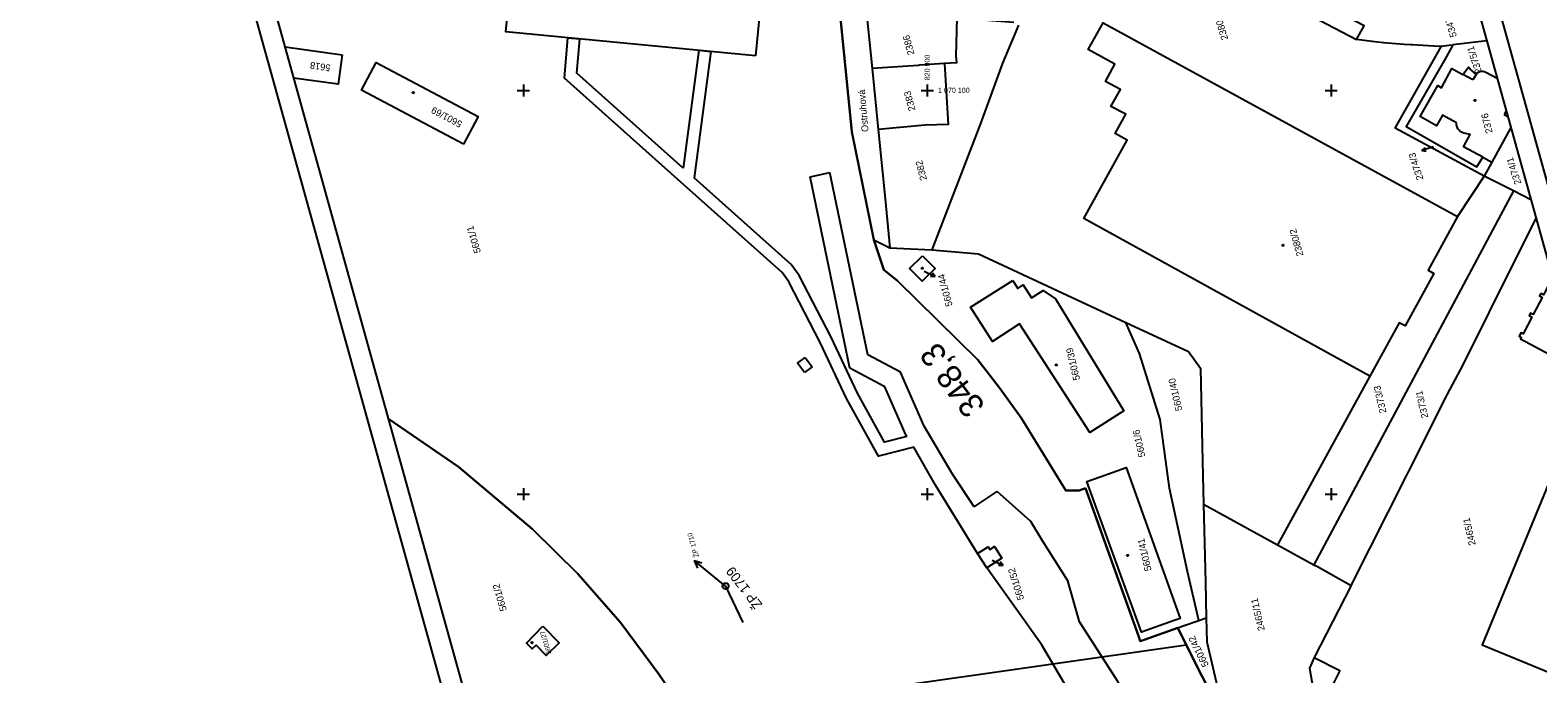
# Model space of a CAD drawing. Extents: x -821122 to -820555, y -1070892 to -1069801.
# Drawn here: x -821122.1 to -820748.9, y -1070244.5 to -1070085.1 of the extents above; entities that cross this region are included whole.
import ezdxf

# ---------------------------------------------------------------- set-up
doc = ezdxf.new("R2010")
doc.units = 0
for name, color, linetype in [('Hranice drážního pozemku', 7, 'Continuous'), ('Hranice parcel', 7, 'Continuous'), ('Katastrální hranice', 7, 'Continuous'), ('Parcelní čísla', 7, 'Continuous'), ('Pop  PČ popisy', 7, 'Continuous'), ('Ram', 7, 'Continuous'), ('Sttaniceni a namezniky', 7, 'Continuous'), ('Vnitřní kresba', 7, 'Continuous'), ('Vrstva 61', 7, 'Continuous'), ('Vrstva 63', 7, 'Continuous'), ('ZBP', 7, 'Continuous'), ('Značky budov', 7, 'Continuous')]:
    doc.layers.add(name, color=color, linetype=linetype)

msp = doc.modelspace()

# ---------------------------------------------------------------- linework, layer by layer
at = {"layer": 'Hranice drážního pozemku'}
for p, q in [((-820907.37, -1070147.11), (-820887.52, -1070166.75)), ((-820860.8, -1070198.48), (-820847.74, -1070235.07)), ((-820838.01, -1070233.1), (-820835.88, -1070237.32)), ((-820835.88, -1070237.32), (-820826.1, -1070256.7))]:
    msp.add_line(p, q, dxfattribs=at)
for points in [[(-820922.5, -1070043.2), (-820922.83, -1070068.79), (-820918.68, -1070110.25), (-820913.23, -1070137.01)], [(-820913.23, -1070137.01), (-820910.8, -1070144.4), (-820907.37, -1070147.11)], [(-820887.52, -1070166.75), (-820882.1, -1070173.67), (-820876.76, -1070181.11), (-820865.67, -1070199.11), (-820862.44, -1070199.07), (-820860.8, -1070198.48)], [(-820959.73, -1070254.91), (-820961.88, -1070251.33), (-820966.49, -1070244.53), (-820975.99, -1070231.76), (-820986.52, -1070219.72), (-820997.71, -1070208.62), (-821016.02, -1070193.21), (-821033.38, -1070181.32)], [(-820847.74, -1070235.07), (-820847.27, -1070236.4), (-820846.3, -1070236.05), (-820838.01, -1070233.1)]]:
    msp.add_lwpolyline(points, dxfattribs=at)
at = {"layer": 'Hranice parcel'}
for p, q in [((-820914.97, -1070081.64), (-820913.68, -1070094.59)), ((-820761.51, -1070087.73), (-820769.91, -1070088.69)), ((-820913.68, -1070094.59), (-820912.16, -1070109.68)), ((-820761.74, -1070095.44), (-820758.95, -1070096.96)), ((-820762.46, -1070116.53), (-820760.23, -1070117.74)), ((-820760.23, -1070117.74), (-820762.14, -1070121.26)), ((-820762.14, -1070121.26), (-820768.74, -1070131.25)), ((-820754.91, -1070124.89), (-820762.14, -1070121.26)), ((-820754.91, -1070124.89), (-820804.28, -1070217.45)), ((-820750.59, -1070127.06), (-820754.91, -1070124.89)), ((-820913.23, -1070137.01), (-820909.27, -1070138.99)), ((-820909.27, -1070138.99), (-820898.88, -1070139.5)), ((-820790.41, -1070170.74), (-820813.34, -1070212.53)), ((-820831.6, -1070202.47), (-820813.34, -1070212.53)), ((-820813.34, -1070212.53), (-820804.28, -1070217.45)), ((-820795.08, -1070222.64), (-820804.2, -1070240.46)), ((-820832.77, -1070231.24), (-820830.93, -1070230.58)), ((-820959.73, -1070254.91), (-820835.88, -1070237.32))]:
    msp.add_line(p, q, dxfattribs=at)
for points in [[(-820793.74, -1070087.35), (-820791.84, -1070083.97), (-820852.05, -1070052.56)], [(-820845, -1070059.46), (-820842.81, -1070061.6), (-820793.74, -1070087.35)], [(-820942.5, -1070091.4), (-821004.34, -1070085.47), (-821002.76, -1070069.27), (-820940.94, -1070075.3), (-820942.5, -1070091.4)], [(-820878.59, -1070083.2), (-820892.71, -1070082.07), (-820892.93, -1070091.44), (-820892.8, -1070093.17), (-820895.78, -1070093.35)], [(-820790.41, -1070170.74), (-820861.21, -1070131.75), (-820850.55, -1070112.3), (-820853.49, -1070110.66), (-820850.87, -1070105.91), (-820854.53, -1070103.94), (-820852.21, -1070099.75), (-820855.86, -1070097.75), (-820853.56, -1070093.52), (-820860.16, -1070089.86), (-820856.47, -1070083.21), (-820768.74, -1070131.25)], [(-820877.39, -1070083.81), (-820881.36, -1070093.26), (-820886.87, -1070108.2), (-820898.88, -1070139.5)], [(-821058.98, -1070089.19), (-821044.85, -1070091.16)], [(-820772.69, -1070089.01), (-820773.3, -1070089.08), (-820778.55, -1070088.78), (-820779.81, -1070088.72), (-820780.38, -1070088.7), (-820781.94, -1070088.59), (-820785.02, -1070088.37), (-820787.06, -1070088.17), (-820789.85, -1070087.9), (-820793.74, -1070087.35)], [(-820762.14, -1070121.26), (-820784.18, -1070109.3), (-820772.69, -1070089.01)], [(-820769.91, -1070088.69), (-820770.16, -1070089.16), (-820771.84, -1070092.31), (-820781.49, -1070108.94), (-820763.99, -1070118.89), (-820762.46, -1070116.53)], [(-820772.69, -1070089.01), (-820770.9, -1070088.8), (-820769.91, -1070088.69)], [(-821044.85, -1070091.16), (-821045.87, -1070098.45), (-821056.83, -1070096.93)], [(-821014.82, -1070113.27), (-821040.04, -1070099.95), (-821036.4, -1070093.07), (-821011.18, -1070106.44), (-821014.82, -1070113.27)], [(-820895.78, -1070093.35), (-820901.94, -1070093.75), (-820902.26, -1070093.79), (-820913.68, -1070094.59)], [(-820895.78, -1070093.35), (-820894.81, -1070108.42), (-820900.5, -1070108.58), (-820912.16, -1070109.68)], [(-820768.98, -1070108.05), (-820772.42, -1070106.09), (-820773.94, -1070108.73), (-820777.98, -1070106.46), (-820773.64, -1070098.8), (-820772.69, -1070099.31), (-820770.13, -1070094.55), (-820767.42, -1070096.02), (-820765.99, -1070094.23), (-820765.59, -1070094.6), (-820765.72, -1070094.75), (-820764.15, -1070096.03)], [(-820764.15, -1070096.03), (-820763.88, -1070095.7), (-820763.55, -1070095.45), (-820763.37, -1070095.36), (-820762.97, -1070095.23), (-820762.55, -1070095.2), (-820762.13, -1070095.27), (-820761.74, -1070095.44)], [(-820767.16, -1070110.57), (-820767.62, -1070110.4), (-820768.04, -1070110.14), (-820768.35, -1070109.86), (-820768.64, -1070109.47), (-820768.85, -1070109.02), (-820768.96, -1070108.54), (-820768.98, -1070108.05)], [(-820755.54, -1070109.21), (-820760.23, -1070117.74)], [(-820912.16, -1070109.68), (-820910.42, -1070126.82), (-820909.27, -1070138.99)], [(-820762.46, -1070116.53), (-820767.25, -1070113.93), (-820765.63, -1070110.94), (-820767.16, -1070110.57)], [(-820795.08, -1070222.64), (-820781.27, -1070195.24), (-820780.8, -1070194.32), (-820771.51, -1070175.9), (-820771.18, -1070175.25), (-820768.01, -1070169.15), (-820764.04, -1070161.33), (-820757.67, -1070148.47), (-820749.29, -1070131.72)], [(-820768.74, -1070131.25), (-820776.02, -1070144.51), (-820774.57, -1070145.3), (-820781.7, -1070158.3), (-820783.17, -1070157.57), (-820790.41, -1070170.74)], [(-820901.18, -1070140.95), (-820898.08, -1070144.08), (-820901.29, -1070147.27), (-820904.4, -1070144.11), (-820901.18, -1070140.95)], [(-820898.88, -1070139.5), (-820887.34, -1070140.5), (-820850.84, -1070157.46)], [(-820745.47, -1070145.47), (-820745.83, -1070146.18), (-820745.32, -1070146.44), (-820747.47, -1070150.59), (-820748.14, -1070150.25), (-820748.48, -1070150.89), (-820747.81, -1070151.24), (-820750, -1070155.48), (-820750.67, -1070155.13), (-820751, -1070155.76), (-820750.33, -1070156.11), (-820752.51, -1070160.31), (-820753.01, -1070160.04), (-820753.44, -1070160.87), (-820752.94, -1070161.14), (-820753.12, -1070161.49), (-820738.91, -1070169.09)], [(-820878.86, -1070147.05), (-820877.61, -1070149.01), (-820876.24, -1070148.14), (-820874.2, -1070151.37), (-820871.31, -1070149.54), (-820868.25, -1070151.57), (-820851.33, -1070179.37), (-820859.8, -1070184.75), (-820877.14, -1070157.82), (-820883.85, -1070162.18), (-820889.3, -1070153.67), (-820878.86, -1070147.05)], [(-820832.77, -1070231.24), (-820835.57, -1070219.11), (-820840.04, -1070198.5), (-820842.31, -1070181.46), (-820847.5, -1070165.14), (-820850.84, -1070157.46)], [(-820850.84, -1070157.46), (-820835.36, -1070164.66), (-820832.35, -1070168.8), (-820831.85, -1070191.82), (-820831.6, -1070202.47)], [(-821033.38, -1070181.32), (-821016.02, -1070193.21), (-820997.71, -1070208.62), (-820986.52, -1070219.72), (-820975.99, -1070231.76), (-820966.49, -1070244.53), (-820961.88, -1070251.33), (-820959.73, -1070254.91)], [(-820735.08, -1070182.87), (-820737.59, -1070187.13), (-820741.52, -1070185.98), (-820762.61, -1070237.26), (-820745.8, -1070244.23), (-820729.31, -1070203.63)], [(-820838.92, -1070231.3), (-820846.98, -1070234.17), (-820860.48, -1070196.84), (-820857.17, -1070195.66), (-820850.78, -1070193.39), (-820837.36, -1070230.75), (-820838.92, -1070231.3)], [(-820831.6, -1070202.47), (-820831.16, -1070221.77), (-820830.93, -1070230.58)], [(-820885.29, -1070218.2), (-820887.54, -1070214.67), (-820884.92, -1070213), (-820884.49, -1070213.68), (-820883.39, -1070212.98), (-820881.58, -1070215.81), (-820885.29, -1070218.2)], [(-820804.28, -1070217.45), (-820803.44, -1070217.91), (-820795.08, -1070222.64)], [(-820995.15, -1070232.68), (-820991.13, -1070236.82), (-820994.37, -1070239.98), (-820996.87, -1070237.37), (-820997.84, -1070238.33), (-820999.26, -1070236.86), (-820995.15, -1070232.68)], [(-820838.01, -1070233.1), (-820836.68, -1070232.63), (-820832.77, -1070231.24)], [(-820830.93, -1070230.58), (-820830.77, -1070236.59), (-820826.1, -1070256.7)], [(-820804.2, -1070240.46), (-820805.38, -1070243.04), (-820804.45, -1070248.28), (-820803.2, -1070254.4)], [(-820804.2, -1070240.46), (-820797.83, -1070243.67), (-820803.2, -1070254.4)]]:
    msp.add_lwpolyline(points, dxfattribs=at)
at = {"layer": 'Katastrální hranice'}
for p, q in [((-820887.52, -1070166.75), (-820907.37, -1070147.11)), ((-820847.74, -1070235.07), (-820860.8, -1070198.48)), ((-820835.88, -1070237.32), (-820838.01, -1070233.1)), ((-820826.1, -1070256.7), (-820835.88, -1070237.32))]:
    msp.add_line(p, q, dxfattribs=at)
for points in [[(-820913.23, -1070137.01), (-820918.68, -1070110.25), (-820922.83, -1070068.79), (-820922.5, -1070043.2)], [(-820907.37, -1070147.11), (-820910.8, -1070144.4), (-820913.23, -1070137.01)], [(-820860.8, -1070198.48), (-820862.44, -1070199.07), (-820865.67, -1070199.11), (-820876.76, -1070181.11), (-820882.1, -1070173.67), (-820887.52, -1070166.75)], [(-820838.01, -1070233.1), (-820846.3, -1070236.05), (-820847.27, -1070236.4), (-820847.74, -1070235.07)]]:
    msp.add_lwpolyline(points, dxfattribs=at)
at = {"layer": 'Pop  PČ popisy'}
for p, q in [((-820774.72, -1070113.97), (-820777.57, -1070114.9)), ((-820777.57, -1070114.9), (-820776.78, -1070114.11)), ((-820777.57, -1070114.9), (-820776.47, -1070115.06)), ((-820900.77, -1070144.79), (-820898.07, -1070146.11)), ((-820898.07, -1070146.11), (-820899.19, -1070146.12)), ((-820898.07, -1070146.11), (-820898.75, -1070145.22)), ((-820883.94, -1070216.35), (-820881.24, -1070217.66)), ((-820881.24, -1070217.66), (-820882.36, -1070217.67)), ((-820881.24, -1070217.66), (-820881.92, -1070216.77))]:
    msp.add_line(p, q, dxfattribs=at)
at = {"layer": 'Ram'}
for points in [[(-820835.94, -1069801.19), (-820554.83, -1070812.86)], [(-820837.51, -1070886.22), (-821115.94, -1069884.19), (-820839.42, -1069807.35)], [(-820839.42, -1069807.35), (-820560.99, -1070809.39)], [(-820840.99, -1070892.38), (-821122.1, -1069880.71)]]:
    msp.add_lwpolyline(points, dxfattribs=at)
at = {"layer": 'Vnitřní kresba'}
for p, q in [((-820764.96, -1070097.36), (-820767.42, -1070096.02)), ((-820764.15, -1070096.03), (-820764.96, -1070097.36)), ((-820756.69, -1070105.08), (-820757.17, -1070105.96)), ((-820757.17, -1070105.96), (-820756.32, -1070106.43)), ((-820932.15, -1070167.55), (-820930.22, -1070166.12)), ((-820930.43, -1070169.88), (-820932.15, -1070167.55)), ((-820928.5, -1070168.46), (-820930.43, -1070169.88)), ((-820930.22, -1070166.12), (-820928.5, -1070168.46))]:
    msp.add_line(p, q, dxfattribs=at)
at = {"layer": 'Vrstva 61'}
for p, q in [((-821001.5, -1070100), (-820998.5, -1070100)), ((-821000, -1070098.5), (-821000, -1070101.5)), ((-820901.5, -1070100), (-820898.5, -1070100)), ((-820900, -1070098.5), (-820900, -1070101.5)), ((-820801.5, -1070100), (-820798.5, -1070100)), ((-820800, -1070098.5), (-820800, -1070101.5)), ((-821000, -1070198.5), (-821000, -1070201.5)), ((-820900, -1070198.5), (-820900, -1070201.5)), ((-820800, -1070198.5), (-820800, -1070201.5)), ((-821001.5, -1070200), (-820998.5, -1070200)), ((-820901.5, -1070200), (-820898.5, -1070200)), ((-820801.5, -1070200), (-820798.5, -1070200))]:
    msp.add_line(p, q, dxfattribs=at)
at = {"layer": 'Vrstva 63'}
for p, q in [((-820989.01, -1070086.94), (-820986.02, -1070087.23)), ((-820956.59, -1070090.05), (-820960.4, -1070119.21)), ((-820953.6, -1070090.34), (-820957.69, -1070121.63)), ((-820956.59, -1070090.05), (-820953.6, -1070090.34)), ((-820929.03, -1070121.35), (-820924.13, -1070120.33)), ((-820888.38, -1070203.11), (-820882.74, -1070199.34))]:
    msp.add_line(p, q, dxfattribs=at)
for points in [[(-820843.48, -1070284.13), (-820843.93, -1070282.84), (-820847.81, -1070277.93), (-820871.73, -1070237.25), (-820885.29, -1070218.2), (-820887.54, -1070214.67), (-820897.96, -1070197.77), (-820903.32, -1070188.38), (-820912.12, -1070190.61), (-820919.97, -1070176.29), (-820926.49, -1070162.4), (-820934.28, -1070147.4), (-820935.96, -1070145.11), (-820960.28, -1070123.34), (-820989.85, -1070096.95), (-820989.01, -1070086.94)], [(-820960.4, -1070119.21), (-820986.73, -1070095.71), (-820986.02, -1070087.23)], [(-820888.38, -1070203.11), (-820893.8, -1070195), (-820900.76, -1070183.17), (-820906.67, -1070169.8), (-820914.74, -1070165.47), (-820924.13, -1070120.33)], [(-820905.06, -1070185.73), (-820910.61, -1070187.13), (-820917.29, -1070174.93), (-820923.8, -1070161.07), (-820931.72, -1070145.81), (-820933.72, -1070143.08), (-820957.69, -1070121.63)], [(-820905.06, -1070185.73), (-820905.22, -1070185.45), (-820910.55, -1070173.4), (-820919.16, -1070168.77), (-820929.03, -1070121.35)], [(-820833.99, -1070279.04), (-820843.49, -1070262.96), (-820852.87, -1070246.42), (-820862.31, -1070231.6), (-820865.19, -1070221.48), (-820871.51, -1070211.52), (-820874.37, -1070206.78), (-820882.74, -1070199.34)]]:
    msp.add_lwpolyline(points, dxfattribs=at)
at = {"layer": 'ZBP'}
for p, q in [((-820949.94, -1070222.75), (-820957.7, -1070216.44)), ((-820957.7, -1070216.44), (-820955.78, -1070217.01)), ((-820957.7, -1070216.44), (-820956.92, -1070218.28)), ((-820949.93, -1070222.8), (-820949.95, -1070222.71)), ((-820949.94, -1070222.75), (-820945.66, -1070231.79))]:
    msp.add_line(p, q, dxfattribs=at)
msp.add_circle((-820949.94, -1070222.75), 0.756, dxfattribs=at)
at = {"layer": 'Značky budov'}
for centre in [(-821027.27, -1070100.52), (-820764.44, -1070102.48), (-820811.94, -1070138.33), (-820901.26, -1070144.02), (-820868.06, -1070167.98), (-820850.4, -1070215.15), (-820997.86, -1070236.77)]:
    msp.add_circle(centre, 0.175, dxfattribs=at)

# ---------------------------------------------------------------- texts
at = {"layer": 'Parcelní čísla'}
for s, height, rotation, p in [('2380/1', 1.7, 106.8818, (-820825.49, -1070087.22)), ('5347/4', 1.7, 105.9528, (-820768.88, -1070086.56)), ('2386', 1.7, 105.4573, (-820903.14, -1070090.99)), ('2375/1', 1.7, 108.0352, (-820762.65, -1070095.46)), ('5618', 1.7, 172, (-821047.67, -1070093.62)), ('2383', 1.7, 104.888, (-820902.9, -1070104.86)), ('5601/69', 1.7, 152.0392, (-821014.96, -1070107.79)), ('2376', 1.7, 104.4181, (-820760.02, -1070110.39)), ('2374/3', 1.7, 107.672, (-820777.16, -1070121.9)), ('2374/1', 1.7, 108.0778, (-820752.9, -1070123)), ('2382', 1.7, 104.4012, (-820900.06, -1070122.06)), ('5601/1', 1.7, 106.434, (-821010.48, -1070140.04)), ('2380/2', 1.7, 105.6584, (-820806.86, -1070140.81)), ('5601/44', 1.7, 104.5638, (-820893.72, -1070153.26)), ('5601/39', 1.7, 103, (-820862.17, -1070171.6)), ('5601/40', 1.7, 103, (-820836.84, -1070179.14)), ('2373/3', 1.7, 103, (-820786.32, -1070179.72)), ('2373/1', 1.7, 103, (-820775.95, -1070180.98)), ('5601/6', 1.7, 103, (-820845.97, -1070190.63)), ('2465/1', 1.7, 103, (-820764.21, -1070212.48)), ('5601/41', 1.7, 103, (-820844.47, -1070218.82)), ('5601/52', 1.7, 107.2623, (-820875.99, -1070225.93)), ('5601/2', 1.7, 106.0622, (-821004.07, -1070228.69)), ('2465/11', 1.7, 103, (-820816.43, -1070233.61)), ('5601/27', 1.2, 106.0523, (-820993.09, -1070239.46)), ('5601/42', 1.7, 116, (-820830.27, -1070242.29))]:
    msp.add_text(s, height=height, rotation=rotation, dxfattribs=at).set_placement(p)
at = {"layer": 'Pop  PČ popisy'}
msp.add_text('Ostruhová', height=1.7, rotation=95, dxfattribs=at).set_placement((-820914.54, -1070110.2))
at = {"layer": 'Sttaniceni a namezniky'}
msp.add_text('348,3', height=6, rotation=126.6591, dxfattribs=at).set_placement((-820885.45, -1070178.06))
at = {"layer": 'Vrstva 61'}
msp.add_text('820 900', height=1.275, rotation=90, dxfattribs=at).set_placement((-820899.39, -1070097.48))
msp.add_text('1 070 100', height=1.275, dxfattribs=at).set_placement((-820897.34, -1070100.59))
at = {"layer": 'ZBP'}
for s, height, rotation, p in [('ŽP 1710', 1.2, 106.2751, (-820956.53, -1070215.44)), ('ŽP 1709', 2.4, 127.6398, (-820940.7, -1070227.28))]:
    msp.add_text(s, height=height, rotation=rotation, dxfattribs=at).set_placement(p)

doc.saveas('drawing.dxf')
